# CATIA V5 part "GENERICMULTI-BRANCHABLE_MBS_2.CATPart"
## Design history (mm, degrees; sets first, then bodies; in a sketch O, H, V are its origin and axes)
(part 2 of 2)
Set2
  Point28: (26210.8971, -6435.7247, 4603.2986)
  Point29: (26215.4315, -6450.7231, 4604.875)
  Point30: (26226.549, -6511.792, 4617.8488)
  Point31: (26245.2256, -6611.3388, 4712.8284)
  Point32: (26253.0624, -6634.1244, 4720.3563)
  Point33: (26259.7202, -6648.3176, 4721.8481)
  Point34: (26275.8018, -6666.6772, 4727.9073)
  Point35: (26335.5883, -6717.1276, 4753.1798)
  Point36: (26342.2461, -6731.3208, 4754.6715)
  Point37: (26395.6331, -6861.6582, 4772.8892)
  Point38: (26410.3313, -6892.9906, 4776.1824)
  Point39: (26479.8206, -7055.6468, 4819.6647)
  Point40: (26495.8411, -7089.7335, 4823.8804)
  Point41: (26551.038, -7189.9079, 4838.589)
  Point42: (26565.7354, -7221.2407, 4841.8823)
  Point43: (26632.0571, -7328.9113, 4852.9491)
  Point44: (26679.4305, -7421.1473, 4862.4419)
  Point45: (26682.0816, -7461.9849, 4866.7341)
  Point46: (26905.0574, -6420.2887, 4628.5373)
  Point47: (26889.4644, -6421.085, 4630.5929)
  Point48: (26769.6982, -6514.171, 4661.0029)
  Point49: (26754.2269, -6514.8756, 4663.8559)
  Point50: (26624.1378, -6521.3537, 4682.5751)
  Point51: (26608.6664, -6522.0583, 4685.4281)
  Point52: (26413.9644, -6534.2296, 4732.5096)
  Point53: (26398.4931, -6534.9342, 4735.3627)
  Point54: (27024.2386, -7381.9664, 4835.9189)
  Point55: (26986.6651, -7386.5261, 4839.7779)
  Point56: (26970.9498, -7387.5352, 4839.8839)
  Point57: (26808.9095, -7393.0417, 4851.0574)
  Point58: (26793.1942, -7394.0508, 4851.1634)
  Point59: (26768.0241, -7391.3643, 4851.5508)
  Point60: (26009.113, -5543.4271, 4613.7933)
  Point61: (25993.5231, -5542.252, 4615.6836)
  Point62: (25980.8624, -5541.6778, 4616.3621)
  Point63: (25955.4748, -5541.7244, 4615.7015)
  Point64: (30630.4275, -16002.4289, 5693.8408)
  Point65: (30705.2423, -15998.5304, 5696.7955)
  Point66: (28691.1971, -11794.6414, 5256.3773)
  Point67: (28670.2499, -11804.65, 5298.44)
  Point68: (28669.0489, -11798.0868, 5301.2935)
  Point69: (28701.4338, -11811, 5280.66)
  Point70: (33625.9918, -22357.37, 6307.4056)
  Point71: (33591.8773, -22275.867, 6299.0245)
  Point72: (33574.4809, -22238.7815, 6295.1266)
  Point73: (33519.8177, -22154.4544, 6271.4364)
  Point74: (33513.1598, -22140.2593, 6269.9631)
  Point75: (33507.1355, -22090.1082, 6246.1135)
  Point76: (33500.6949, -22046.4, 6226.4857)
  Point77: (33494.0376, -22032.2065, 6224.9939)
  Point78: (33484.5882, -22012.0594, 6222.8764)
  Point79: (33477.9309, -21997.8659, 6221.3846)
  Point80: (33475.9685, -21954.6179, 6198.9449)
  Point81: (33494.5996, -21868.5206, 6132.2973)
  Point82: (33478.5544, -21834.289, 6128.703)
  Point83: (33437.045, -21791.4844, 6128.8523)
  Point84: (33430.3879, -21777.298, 6127.2937)
  Point85: (33403.5088, -21701.5412, 6120.1851)
  Point86: (33384.3851, -21658.3322, 6115.5983)
  Point87: (33216.1605, -21550.2321, 6164.6795)
  Point88: (33202.0931, -21520.2432, 6161.5275)
  Point89: (33171.6328, -21416.2736, 6215.7513)
  Point90: (33154.7081, -21380.1941, 6211.9592)
  Point91: (33113.7558, -21329.0956, 6215.7511)
  Point92: (33107.1338, -21314.8083, 6215.8907)
  Point93: (33072.4689, -21240.6323, 6204.5785)
  Point94: (33066.3204, -21228.1565, 6197.1926)
  Point95: (33063.3332, -21193.9624, 6154.1145)
  Point96: (33063.958, -21196.9265, 6138.6606)
  Point97: (33086.9496, -21176.3228, 6087.6176)
  Point98: (33080.2119, -21162.1675, 6086.1236)
  Point99: (33081.1473, -21112.1586, 6041.3205)
  Point100: (33094.7819, -21106.0865, 6038.241)
  Point101: (33197.1818, -21075.543, 6039.3942)
  Point102: (33210.7246, -21068.9472, 6041.7062)
  Point103: (33219.0949, -21016.8368, 6167.5047)
  Point104: (33236.2184, -20984.8219, 6165.6873)
  Point105: (33281.5846, -20889.2469, 6154.8349)
  Point106: (33232.6912, -20791.7129, 6145.3265)
  Point107: (33133.4795, -20582.1148, 6123.4695)
  Point108: (33082.6288, -20473.2697, 6112.2868)
  Point109: (33000.1394, -20367.0985, 6105.3758)
  Point110: (32992.7933, -20353.8087, 6104.0829)
  Point111: (32910.2958, -20291.16, 6071.9735)
  Point112: (32896.6434, -20297.2536, 6074.9293)
  Point113: (32833.0764, -20269.0874, 6083.636)
  Point114: (32826.4217, -20255.4673, 6082.0654)
  Point115: (32903.1728, -20174.0536, 6081.2833)
  Point116: (32904.2878, -20159.0921, 6078.606)
  Point117: (32859.9782, -20074.0193, 6070.4363)
  Point118: (32851.5252, -20061.3703, 6069.5385)
  Point119: (32799.3008, -19950.3338, 6058.2654)
  Point120: (32793.7359, -19936.2361, 6056.6696)
  Point121: (32750.2195, -19821.8784, 6046.7342)
  Point122: (32735.8599, -19816.9579, 6048.0936)
  Point123: (32674.5765, -19820.0442, 6003.3131)
  Point124: (32660.307, -19826.6913, 6003.7567)
  Point125: (32583.9082, -19872.0605, 6017.9639)
  Point126: (32569.73, -19878.6654, 6018.4046)
  Point127: (32540.01, -19872.6954, 6020.3591)
  Point128: (32518.9809, -19825.699, 6016.2212)
  Point129: (32477.2491, -19779.9413, 6006.7024)
  Point130: (32465.0973, -19770.7942, 6005.7413)
  Point131: (32442.7372, -19754.0865, 6003.9849)
  Point132: (32430.5854, -19744.9394, 6003.0238)
  Point133: (32356.7969, -19675.2218, 5998.2361)
  Point134: (32339.4569, -19646.6856, 6000.1961)
  Point135: (32321.5882, -19619.6259, 6003.4104)
  Point136: (32265.4913, -19534.9454, 6013.4015)
  Point137: (32258.5603, -19521.3914, 6012.6877)
  Point138: (32244.5882, -19491.8466, 6009.7006)
  Point139: (32238.5557, -19478.0022, 6007.6519)
  Point140: (32216.455, -19353.0375, 5954.3605)
  Point141: (32205.2566, -19322.4556, 5951.1462)
  Point142: (32137.3527, -19181.5692, 5929.2341)
  Point143: (32123.1239, -19151.2371, 5926.0461)
  Point144: (32031.1393, -18973.1525, 5905.9509)
  Point145: (32024.4815, -18958.9593, 5904.4592)
  Point146: (32023.0849, -18955.9836, 5904.1464)
  Point147: (32016.4271, -18941.7904, 5902.6546)
  Point148: (31987.9898, -18857.9311, 5897.7993)
  Point149: (31981.332, -18843.7379, 5896.3076)
  Point150: (31973.2781, -18826.5687, 5894.503)
  Point151: (31895.178, -18728.7145, 5918.2594)
  Point152: (31891.3592, -18719.2252, 5930.233)
  Point153: (31886.7397, -18707.7462, 5944.7174)
  Point154: (31888.2493, -18649.8399, 5964.4964)
  Point155: (31871.9, -18614.9864, 5960.8332)
  Point156: (31889.6461, -18549.8491, 5937.2242)
  Point157: (31899.1986, -18546.6401, 5925.1224)
  Point158: (31901.2015, -18545.9672, 5922.5849)
  Point159: (31910.754, -18542.7582, 5910.4831)
  Point160: (31877.1277, -18531.9593, 5851.5927)
  Point161: (31859.6134, -18494.622, 5847.6685)
  Point162: (31864.4727, -18448.0608, 5824.6883)
  Point163: (31882.2702, -18425.6935, 5804.8426)
  Point164: (31845.3081, -18388.6689, 5738.8852)
  Point165: (31796.1069, -18409.9598, 5743.9398)
  Point166: (31743.7772, -18339.3175, 5819.9729)
  Point167: (31729.6971, -18300.8653, 5815.9314)
  Point168: (31695.4689, -18261.9382, 5738.0328)
  Point169: (31679.1093, -18239.0663, 5719.8677)
  Point170: (31672.4495, -18224.8739, 5718.376)
  Point171: (31666.8102, -18212.8562, 5717.1129)
  Point172: (31660.1505, -18198.6639, 5715.6212)
  Point173: (31654.0114, -18174.8123, 5714.0439)
  Point174: (31560.2361, -18001.7562, 5744.2096)
  Point175: (31640.511, -18093.1795, 5709.2052)
  Point176: (31634.0679, -18079.4441, 5707.7615)
  Point177: (31626.3258, -18062.9395, 5706.0268)
  Point178: (31542.6491, -17993.4268, 5802.3087)
  Point179: (31542.061, -17993.3884, 5817.6286)
  Point180: (31542.6484, -17989.1748, 5842.7504)
  Point181: (31548.165, -17916.202, 5890.3271)
  Point182: (31542.9754, -17902.2088, 5890.0312)
  Point183: (31533.4855, -17884.9082, 5887.038)
  Point184: (31443.4175, -17715.3779, 5873.3952)
  Point185: (31440.115, -17705.3606, 5862.2142)
  Point186: (31432.8362, -17691.7603, 5851.2808)
  Point187: (31415.8055, -17650.5175, 5846.4479)
  Point188: (31411.8896, -17637.1481, 5852.8491)
  Point189: (31405.1236, -17622.5543, 5863.3297)
  Point190: (31354.4803, -17503.9302, 5847.0211)
  Point191: (31348.0372, -17490.1948, 5845.5775)
  Point192: (31340.4665, -17474.0557, 5843.8812)
  Point193: (31257.9077, -17297.6107, 5827.7879)
  Point194: (31251.4646, -17283.8754, 5826.3443)
  Point195: (31243.8938, -17267.7362, 5824.648)
  Point196: (31152.9573, -17097.0098, 5815.7714)
  Point197: (31149.561, -17086.7279, 5804.9179)
  Point198: (31142.3075, -17073.2391, 5793.5125)
  Point199: (31125.253, -17031.8853, 5789.1502)
  Point200: (31114.4762, -17003.6738, 5806.1811)
  Point201: (31064.5099, -16872.2839, 5789.1628)
  Point202: (31048.4022, -16837.9455, 5785.5537)
  Point203: (31041.9591, -16824.2101, 5784.11)
  Point204: (30970.3729, -16676.6871, 5773.6793)
  Point205: (30960.806, -16660.2145, 5771.9999)
  Point206: (30954.3629, -16646.4792, 5770.5563)
  Point207: (30859.64, -16457.283, 5733.3287)
  Point208: (30843.9973, -16419.3509, 5729.3419)
  Point209: (30838.2144, -16405.3279, 5727.868)
  Point210: (30782.4355, -16282.6087, 5717.8185)
  Point211: (30772.3702, -16261.1308, 5715.5701)
  Point212: (30765.9332, -16247.392, 5714.1314)
  Point213: (30708.7417, -16124.2162, 5699.0059)
  Point214: (30684.193, -16081.4324, 5694.5243)
  Point215: (30675.0558, -16069.2355, 5694.6099)
  Point216: (30609.1073, -15969.1892, 5681.8985)
  Point217: (30601.1595, -15956.8402, 5669.7645)
  Point218: (30594.8012, -15946.9609, 5660.0572)
  Point219: (30558.2749, -15862.8904, 5639.8917)
  Point220: (30552.1306, -15848.9652, 5639.1206)
  Point221: (30481.7131, -15696.5161, 5633.566)
  Point222: (30478.09, -15683.7803, 5641.1111)
  Point223: (30473.5837, -15667.9388, 5650.4975)
  Point224: (30500.1852, -15610.178, 5643.929)
  Point225: (30506.0524, -15599.4069, 5634.8837)
  Point226: (30513.3863, -15585.943, 5623.577)
  Point227: (30481.875, -15511.385, 5612.8136)
  Point228: (30469.372, -15505.2899, 5619.041)
  Point229: (30453.7432, -15497.6709, 5626.8252)
  Point230: (30432.529, -15486.529, 5635.0818)
  Point231: (30392.5153, -15436.6701, 5632.7732)
  Point232: (30386.0722, -15422.9348, 5631.3295)
  Point233: (30309.494, -15263.6335, 5602.629)
  Point234: (30303.7114, -15249.6021, 5601.2352)
  Point235: (30267.6852, -15185.3136, 5623.3991)
  Point236: (30261.2421, -15171.5783, 5621.9554)
  Point237: (30253.1882, -15154.4091, 5620.1509)
  Point238: (30223.7367, -15091.3522, 5614.1618)
  Point239: (30217.2936, -15077.6168, 5612.7182)
  Point240: (30209.7229, -15061.4778, 5611.0219)
  Point241: (30173.8339, -14980.1156, 5579.7054)
  Point242: (30168.0514, -14966.0843, 5578.3116)
  Point243: (30101.7641, -14839.6682, 5562.0667)
  Point244: (30095.321, -14825.9329, 5560.6231)
  Point245: (30083.5087, -14800.7514, 5557.9764)
  Point246: (30028.5562, -14655.28, 5566.0123)
  Point247: (30022.7737, -14641.2487, 5564.6185)
  Point248: (30015.5455, -14623.7096, 5562.8762)
  Point249: (29954.4805, -14510.1131, 5560.7587)
  Point250: (29948.0374, -14496.3777, 5559.315)
  Point251: (29939.8552, -14480.5225, 5557.6486)
  Point252: (29878.1587, -14353.2851, 5511.2557)
  Point253: (29871.7182, -14339.5486, 5509.812)
  Point254: (29859.3461, -14312.9429, 5507.1017)
  Point255: (29803.7409, -14191.2152, 5516.5961)
  Point256: (29797.9584, -14177.1839, 5515.2023)
  Point257: (29789.7665, -14157.3062, 5513.2277)
  Point258: (29722.8521, -14055.9056, 5475.1692)
  Point259: (29708.6378, -14025.6027, 5471.9842)
  Point260: (29636.0444, -13881.7179, 5493.3194)
  Point261: (29630.2628, -13867.6671, 5492.133)
  Point262: (29618.1504, -13740.5321, 5468.3083)
  Point263: (29611.7073, -13726.7967, 5466.8646)
  Point264: (29499.8817, -13598.3959, 5469.0726)
  Point265: (29494.0992, -13584.3646, 5467.6788)
  Point266: (29477.2398, -13499.2912, 5469.2036)
  Point267: (29470.5619, -13474.8598, 5468.8534)
  Point268: (29464.1188, -13461.1244, 5467.4098)
  Point269: (29456.065, -13443.9552, 5465.6052)
  Point270: (29438.3465, -13406.183, 5461.6352)
  Point271: (29431.9034, -13392.4476, 5460.1915)
  Point272: (29423.8495, -13375.2784, 5458.387)
  Point273: (29391.0631, -13313.3142, 5438.5464)
  Point274: (29385.2805, -13299.2829, 5437.1526)
  Point275: (29378.0524, -13281.7437, 5435.4103)
  Point276: (29303.7982, -13125.812, 5382.0098)
  Point277: (29297.3551, -13112.0766, 5380.5661)
  Point278: (29289.3152, -13094.9372, 5378.7647)
  Point279: (29232.4259, -12971.8865, 5382.2026)
  Point280: (29225.9828, -12958.1511, 5380.759)
  Point281: (29217.9429, -12941.0117, 5378.9576)
  Point282: (29166.4167, -12820.2745, 5390.5875)
  Point283: (29160.6342, -12806.2432, 5389.1936)
  Point284: (29153.4061, -12788.7041, 5387.4513)
  Point285: (29089.186, -12657.5785, 5347.5585)
  Point286: (29082.7429, -12643.8431, 5346.1149)
  Point287: (29074.703, -12626.7037, 5344.3134)
  Point288: (29021.8985, -12509.0042, 5346.3303)
  Point289: (29016.116, -12494.9729, 5344.9364)
  Point290: (29005.5147, -12469.2488, 5342.3811)
  Point291: (28970.852, -12374.9198, 5344.808)
  Point292: (28964.3494, -12361.2248, 5343.2525)
  Point293: (28876.6158, -12197.8503, 5315.4594)
  Point294: (28870.8333, -12183.819, 5314.0656)
  Point295: (28860.232, -12158.0949, 5311.5102)
  Point296: (28825.2125, -12104.0607, 5306.923)
  Point297: (28818.9677, -12092.93, 5305.8547)
  Point298: (28812.5246, -12079.1947, 5304.4111)
  Point299: (28787.1818, -12025.1689, 5298.7327)
  Point300: (28758.7647, -11952.5396, 5300.2549)
  Point301: (28746.0133, -11919.3772, 5299.7529)
  Point302: (28740.2308, -11905.3459, 5298.3591)
  Point303: (28733.4364, -11888.8591, 5296.7213)
  Point304: (28676.3466, -11761.6843, 5244.7194)
  Point305: (28670.196, -11747.817, 5243.2618)
  Point306: (28643.3374, -11687.2629, 5236.8977)
  Point307: (28637.1869, -11673.3956, 5235.4401)
  Point308: (28601.2243, -11601.2714, 5228.8516)
  Point309: (28595.0737, -11587.404, 5227.3941)
  Point310: (28568.1685, -11526.5807, 5220.9834)
  Point311: (28561.8949, -11512.7642, 5219.5676)
  Point312: (28556.8149, -11500.0642, 5219.5676)
  Point313: (33719.101, -22231.5732, 6289.4716)
  Point314: (33732.9072, -22225.7127, 6286.7695)
  Point315: (33787.5061, -22276.6101, 6257.841)
  Point316: (25443.4071, -1711.0225, 4806.1879)
  Point317: (25436.3466, -1661.287, 4799.9346)
  Point318: (25436.3466, -1646.047, 4799.9346)
  Point319: (25425.9211, -1805.5957, 4831.3525)
  Point320: (25519.4968, -1709.8297, 4805.2967)
  Point321: (25531.3934, -1661.287, 4799.2903)
  Point322: (25531.3934, -1646.047, 4799.2903)
  Point323: (25436.3466, -1661.287, 4799.9346)
  Point324: (25436.3466, -1646.047, 4799.9346)
  Point325: (24816.8515, -1857.4459, 4544.5312)
  Point326: (24670.8364, -1917.7, 4527.55)
  Point327: (24505.3861, -1975.2948, 4528.8553)
  Point328: (24491.038, -1975.3029, 4523.7184)
  Point329: (24286.155, -1929.6627, 4442.527)
  Point330: (24285.5539, -1929.3917, 4427.3013)
  Point331: (24285.1492, -1929.6627, 4417.0631)
  Point332: (24284.5482, -1929.3917, 4401.8373)
  Point333: (24284.1479, -1929.7206, 4382.4898)
  Point334: (24283.4331, -1929.7206, 4367.2665)
  Point335: (24267.6572, -1929.6627, 4317.2756)
  Point336: (24267.0562, -1929.3917, 4302.0498)
  Point337: (24266.6519, -1929.6627, 4291.8116)
  Point338: (24266.0509, -1929.3917, 4276.5859)
  Point339: (24252.2418, -1910.0672, 4217.8578)
  Point340: (24251.5594, -1910.0672, 4202.6331)
  Point341: (24246.4541, -1910.0672, 4091.0944)
  Point342: (24245.6601, -1910.0672, 4075.8751)
  Point343: (24254.5566, -1929.6627, 4023.8466)
  Point344: (24253.9556, -1929.3917, 4008.6208)
  Point345: (24253.5501, -1929.6627, 3998.3826)
  Point346: (24252.9491, -1929.3917, 3983.1569)
  Point347: (24282.8711, -1948.4485, 3754.2407)
  Point348: (24282.1563, -1948.4485, 3739.0175)
  Point349: (24427.7771, -1989.7845, 3647.6728)
  Point350: (24437.1603, -2001.7495, 3646.6475)
  Point351: (24428.723, -2080.1437, 3646.8474)
  Point352: (24428.693, -2095.3832, 3646.727)
  Point353: (24426.7322, -2171.6747, 3647.5793)
  Point354: (24430.952, -2186.3091, 3647.0433)
  Point355: (25531.3934, -1661.287, 4799.2903)
  Point356: (25531.3934, -1646.047, 4799.2903)
  Point357: (25436.3466, -1661.287, 4799.9346)
  Point358: (25436.3466, -1646.047, 4799.9346)
  Point359: (25531.3934, -1661.287, 4799.2903)
  Point360: (25531.3934, -1646.047, 4799.2903)
  Point361: (25323.1215, -1824.741, 4834.4069)
  Point362: (25200.1809, -1804.9067, 4791.212)
  Point363: (25187.1306, -1798.4915, 4786.6521)
  Point364: (25141.4446, -1789.4337, 4770.6891)
  Point365: (25127.0576, -1789.4367, 4765.6621)
  Point366: (25036.4443, -1798.3005, 4707.2297)
  Point367: (25022.0573, -1798.3005, 4702.2027)
  Point368: (24910.182, -1846.4358, 4610.8984)
  Point369: (24890.2419, -1846.52, 4597.3166)
  Point370: (24877.6462, -1846.5763, 4588.7373)
  Point371: (24706.8811, -1968.5996, 4455.1513)
  Point372: (24688.6513, -2046.9198, 4440.2516)
  Point373: (24686.6023, -2061.9283, 4438.5768)
  Point374: (24736.2793, -2222.4889, 4385.6882)
  Point375: (24745.4081, -2246.1873, 4385.2306)
  Point376: (24750.8854, -2260.4064, 4384.956)
  Point377: (24817.7957, -2471.2433, 4376.5258)
  Point378: (25324.3871, -1824.8406, 4834.4379)
  Point379: (25339.5689, -1826.169, 4834.5159)
  Point380: (25409.9759, -1809.8769, 4831.352)
  Point381: (25424.6966, -1805.9325, 4831.352)
  Point382 to Point392: stored without definition
  Point393: (30630.4275, -16002.4289, 5693.8408)
  Point394: (30630.4275, -16002.4289, 5693.8408)
  Point395 to Point400: stored without definition
  Point401: (33625.9918, -22357.37, 6307.4056)
  Point402: (33507.1355, -22090.1082, 6246.1135)
  Point403: (33475.9685, -21954.6179, 6198.9449)
  Point404: (32321.5882, -19619.6259, 6003.4104)
  Point405: (31695.4689, -18261.9382, 5738.0328)
  Point406: (31654.0114, -18174.8123, 5714.0439)
  Point407: (31560.2361, -18001.7562, 5744.2096)
  Point408 to Point411: stored without definition
  Point412: (33787.5061, -22276.6101, 6257.841)
  Point413: (33787.5061, -22276.6101, 6257.841)
  Point414 to Point424: stored without definition
  Point425: (26970.375, -6351.8691, 4580.9258)
  Point426: (26970.375, -6351.8691, 4580.9258)
  Point427: (26970.375, -6351.8691, 4580.9258)
  Point428: (26994.5534, -6337.4549, 4571.6059)
  Point429: (27009.4569, -6334.751, 4569.9222)
  Point430: (30522.0317, -15780.7215, 5631.2652)
  Point431: (30528.1697, -15794.4585, 5633.6899)
  Point432: (30853.8571, -16443.26, 5731.8548)
  Point433: (31058.0668, -16858.5485, 5787.7191)
  Point434: (31008.6582, -16755.3691, 5777.0498)
  Point435: (32540.01, -19872.6954, 6020.3591)
  Point436: (32859.3316, -20208.7617, 6084.9051)
  Point437: (32845.6595, -20215.3422, 6086.3289)
  Point438: (33180.0547, -20680.4766, 6131.6914)
  Point439: type OnCurve, Support {line type PtPt, FirstPoint {project ToProject Point466, Support Plane4}, SecondPoint Point466}, RefPoint {project ToProject Point466, Support Plane4}, Length 4.2545
Set3
  Point440 to Point460 "BCPRPoint": linked copy from another document
  Point461 to Point464: linked copy from another document
  Plane1 "BCPPlane": linked copy from another document
  Point465 "BCPRPoint": linked copy from another document
  Plane2 "BCPPlane": linked copy from another document
  Plane3: linked copy from another document
  Plane4: linked copy from another document
  Point466: linked copy from another document
  DatumCurve1: linked copy from another document
  Point467: linked copy from another document
  Plane5: linked copy from another document
  Point468: linked copy from another document
  Plane6: linked copy from another document
  Point469: linked copy from another document
  Plane7: linked copy from another document
  Point470: linked copy from another document
  Plane8: linked copy from another document
  Point471: linked copy from another document
  Plane9: linked copy from another document
  Point472: linked copy from another document
  Plane10 to Plane12: linked copy from another document
  Point473: linked copy from another document
  Point474: linked copy from another document
  Plane13: linked copy from another document
  Plane14: linked copy from another document
  Point475: linked copy from another document
  Point476: linked copy from another document
  Plane15: linked copy from another document
  Plane16: linked copy from another document
Body1 (main body)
